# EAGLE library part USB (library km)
USB-Anschluss Buchse A oder B, mit Schirm
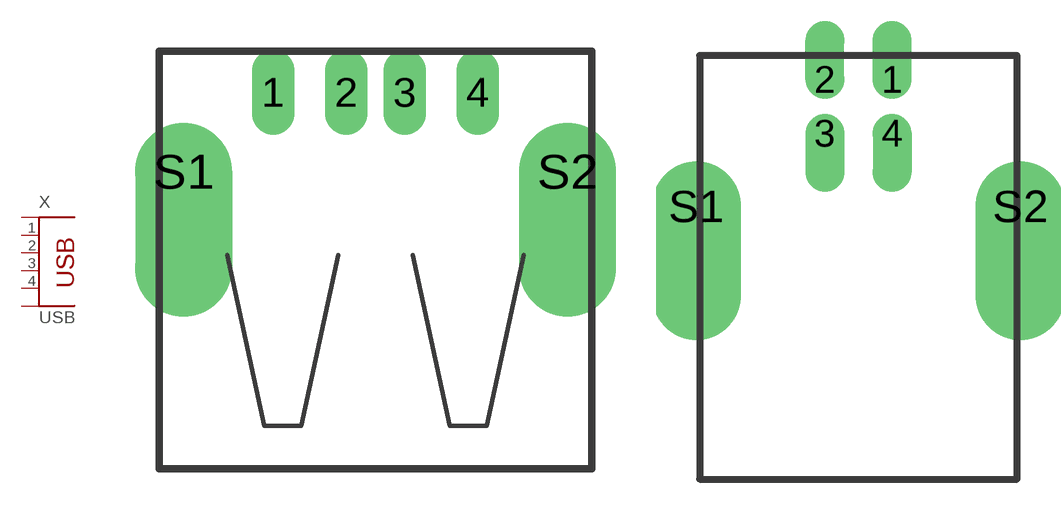
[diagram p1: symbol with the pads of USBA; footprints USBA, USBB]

Designator prefix X

## USBA  [USBA]
1  UCC  pwr
2  D-
3  D+
4  GND  pwr
S1  S  pas
S2  S  pas

## USBB  [USBB]
Pads as for USBA

## Footprint USBA (pad centres in mm)
USB-A-Buchse Durchsteck
drill 0.95 long: 1 -3.5,2.71; 2 -1,2.71; 3 1,2.71; 4 3.5,2.71
drill 2.3 offset: S1 -6.57,0; S2 6.57,0

## Footprint USBB (pad centres in mm)
USB-B-Buchse Durchsteck
drill 0.95 offset: 1 1.25,4.71; 2 -1.25,4.71; 3 -1.25,2.71; 4 1.25,2.71
drill 2.3 offset: S1 -6.02,0; S2 6.02,0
